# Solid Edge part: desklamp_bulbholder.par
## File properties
Author: adamb
Template: Iso Metric Part.par
Last saved by: adamb
Revision: 4
Application: Solid Edge
Username: adamb
Dokumentum tartalom típus: 0
Sűrűség: 0,000 kg/m^3
Pontosság: 0,990
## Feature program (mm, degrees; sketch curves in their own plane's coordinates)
sketch for "unnamed Protrusion 1" plane through (0, 0, 0) normal (0, 0, 1) x-axis (1, 0, 0)
  circle centre (0, 0) radius 8.5
extrude "unnamed Protrusion 1" add finite 40 along +normal
sketch for "Kivágás_1" #1 plane through (0, 0, 0) normal (0, 0, -1) x-axis (-1, 0, 0)
  circle centre (0, 0) radius 4
sketch for "Kivágás_1" #2 plane through (0, 0, 0) normal (0, 0, -1) x-axis (-1, 0, 0)
  circle centre (0, 0) radius 8.5
extrude "Kivágás_1" cut finite 15 along -normal
sketch for "Kivágás_2" plane through (0, 0, 40) normal (0, 0, 1) x-axis (0, 1, 0)
  circle centre (0, 0) radius 7
extrude "Kivágás_2" cut finite 23 along -normal
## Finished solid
Body 1: solid body, 7 faces, 6 edges, 0 vertices.
  Faces by surface: plane 4, cylinder 3
  Edges by curve: circle 6
Bounding box of the edges (mm): 17.000 x 17.000 x 40.000, from (-8.5, -8.5, 0) to (8.5, 8.5, 40).
Cylindrical faces by radius (mm): R4 x1, R7 x1, R8.5 x1
Planar faces by outward normal: +z 2, -z 2
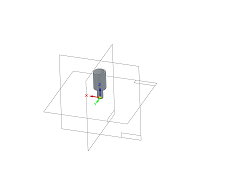
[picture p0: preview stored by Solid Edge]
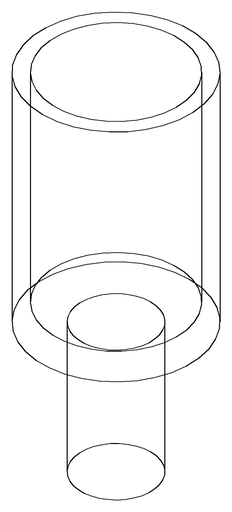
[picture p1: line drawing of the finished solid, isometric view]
